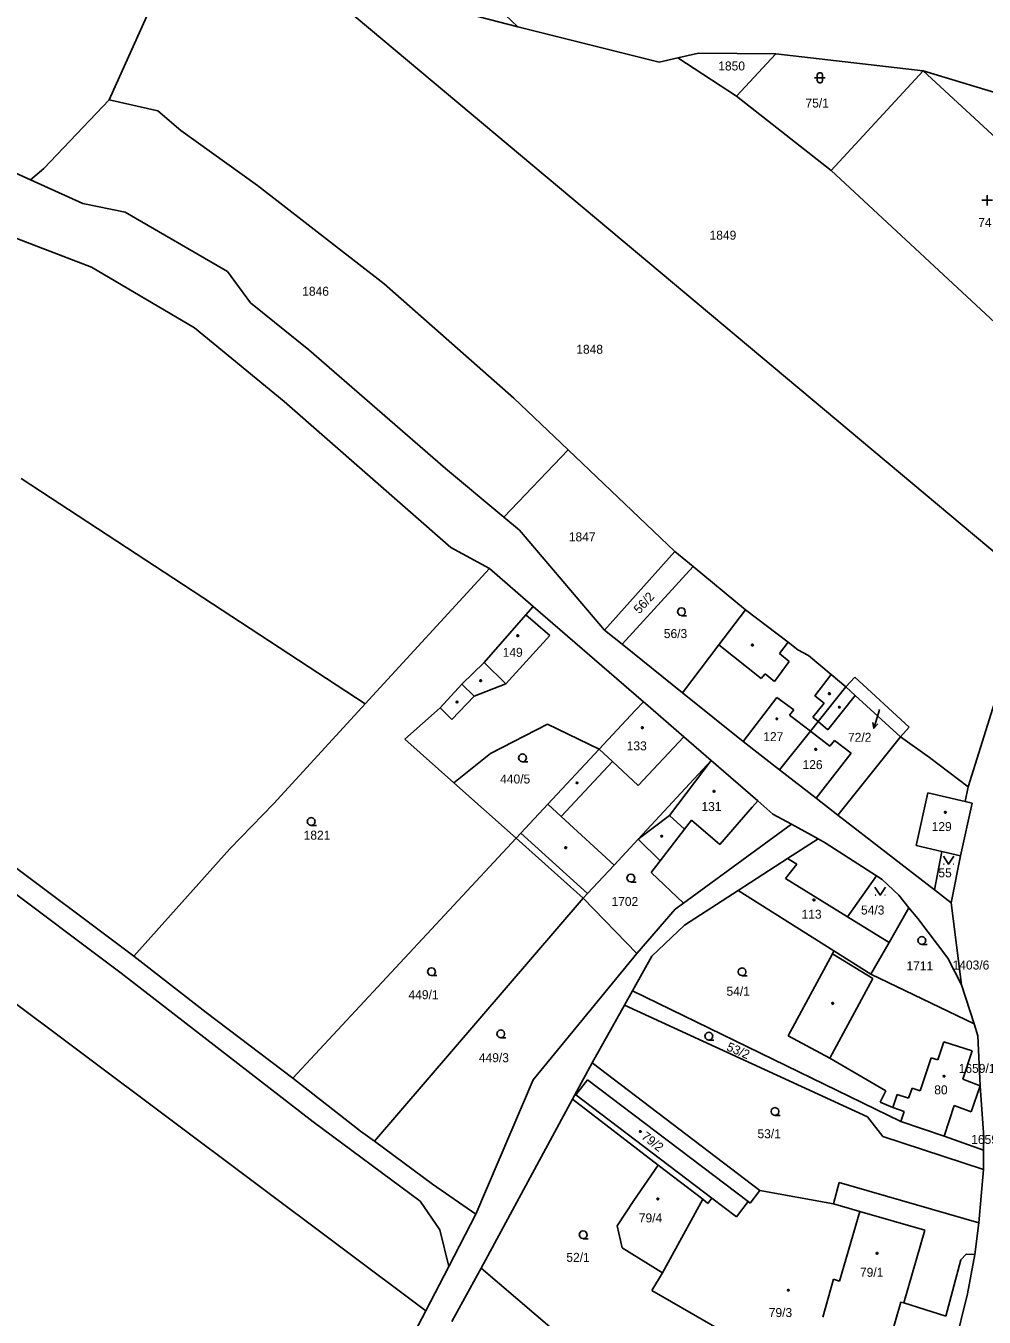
# Model space of a CAD drawing. Extents: x -802857 to -799647, y -1020285 to -1015884.
# Drawn here: x -801671.4 to -801490, y -1017493.5 to -1017248.9 of the extents above; entities that cross this region are included whole.
import ezdxf

# ---------------------------------------------------------------- set-up
doc = ezdxf.new("R2010")
doc.units = 0
for name, color, linetype in [('Default', 7, 'Continuous'), ('KN_HRANICE', 7, 'Continuous'), ('KN_KULTURY', 7, 'Continuous'), ('KN_PARCELY', 7, 'Continuous'), ('KN_SLUCKY', 7, 'Continuous'), ('Železniční svršek', 7, 'Continuous')]:
    doc.layers.add(name, color=color, linetype=linetype)

# ---------------------------------------------------------------- blocks, each defined once
blk = doc.blocks.new('304')
at = {"layer": 'Default'}
blk.add_lwpolyline([(0, 0), (-0.38, 0.1), (-0.65, 0.37), (-0.75, 0.74), (-0.65, 1.11), (-0.38, 1.38), (-0.01, 1.48), (0.36, 1.38), (0.63, 1.11), (0.73, 0.73), (0.63, 0.35), (0.36, 0.08), (-0.02, -0.02), (0.98, -0.02)], dxfattribs=at)
blk = doc.blocks.new('314')
at = {"layer": 'Default'}
for p, q in [((-0.95, 0), (-0.85, 0)), ((0.85, 0), (0.95, 0))]:
    blk.add_line(p, q, dxfattribs=at)
blk.add_lwpolyline([(-1, 1.5), (0, 0), (1, 1.5)], dxfattribs=at)
blk = doc.blocks.new('315')
at = {"layer": 'Default'}
for p, q in [((-1, 1), (1, 1)), ((0, 0), (0, 2))]:
    blk.add_line(p, q, dxfattribs=at)
blk = doc.blocks.new('316')
at = {"layer": 'Default'}
for points in [[(-1, 1), (0.27, 1), (1, 1)], [(-0.5, 1.5), (-0.4, 1.79), (-0.15, 1.97), (0.16, 1.97), (0.41, 1.79), (0.51, 1.5), (0.51, 0.5), (0.41, 0.21), (0.16, 0.03), (-0.15, 0.03), (-0.4, 0.21), (-0.5, 0.5), (-0.5, 1.5)]]:
    blk.add_lwpolyline(points, dxfattribs=at)
blk = doc.blocks.new('NAHRADNI_SYMBOL')
at = {"layer": 'Default'}
blk.add_lwpolyline([(0.09, 0.15), (0.18, 0), (0.09, -0.15), (-0.09, -0.15), (-0.18, 0), (-0.09, 0.15), (0.09, 0.15)], dxfattribs=at)
blk = doc.blocks.new('10292')
at = {"layer": 'Default'}
blk.add_line((0, 3), (0, 0), dxfattribs=at)
blk.add_lwpolyline([(-0.5, 2), (0, 3), (0.5, 2)], dxfattribs=at)
blk = doc.blocks.new('402')
at = {"layer": 'Default'}
blk.add_lwpolyline([(0.09, 0.15), (0.18, 0), (0.09, -0.15), (-0.09, -0.15), (-0.18, 0), (-0.09, 0.15), (0.09, 0.15)], dxfattribs=at)

msp = doc.modelspace()

# ---------------------------------------------------------------- linework, layer by layer
at = {"layer": 'KN_HRANICE'}
for p, q in [((-801655.6, -1017262.96), (-801641.91, -1017232.42)), ((-801619.51, -1017238.39), (-801481.95, -1017353.71)), ((-801578.28, -1017249.11), (-801619.51, -1017238.39)), ((-801578.28, -1017249.11), (-801586.61, -1017241.17)), ((-801551.48, -1017255.81), (-801578.28, -1017249.11)), ((-801551.48, -1017255.81), (-801547.98, -1017255)), ((-801547.98, -1017255), (-801544.09, -1017254.11)), ((-801536.89, -1017262.22), (-801547.98, -1017255)), ((-801544.09, -1017254.11), (-801529.45, -1017254.24)), ((-801529.45, -1017254.24), (-801536.89, -1017262.22)), ((-801501.56, -1017257.45), (-801529.45, -1017254.24)), ((-801518.94, -1017276.33), (-801501.56, -1017257.45)), ((-801477.73, -1017264.63), (-801501.56, -1017257.45)), ((-801466.82, -1017289.45), (-801501.56, -1017257.45)), ((-801655.6, -1017262.96), (-801668, -1017275.97)), ((-801646.39, -1017265.01), (-801655.6, -1017262.96)), ((-801518.94, -1017276.33), (-801536.89, -1017262.22)), ((-801642.06, -1017268.74), (-801646.39, -1017265.01)), ((-801627.56, -1017279.15), (-801642.06, -1017268.74)), ((-801678.51, -1017274.48), (-801670.52, -1017278.09)), ((-801668, -1017275.97), (-801670.52, -1017278.09)), ((-801473.28, -1017318.78), (-801518.94, -1017276.33)), ((-801670.52, -1017278.09), (-801660.59, -1017282.57)), ((-801603.57, -1017297.8), (-801627.56, -1017279.15)), ((-801658.95, -1017294.66), (-801692.48, -1017281.81)), ((-801660.59, -1017282.57), (-801652.6, -1017284.2)), ((-801652.6, -1017284.2), (-801633.2, -1017295.47)), ((-801639.5, -1017306.13), (-801658.95, -1017294.66)), ((-801633.2, -1017295.47), (-801628.86, -1017301.38)), ((-801579.02, -1017319.41), (-801603.57, -1017297.8)), ((-801628.86, -1017301.38), (-801617.81, -1017310.3)), ((-801622.51, -1017320.08), (-801639.5, -1017306.13)), ((-801617.81, -1017310.3), (-801591.97, -1017332.75)), ((-801802.71, -1017316.54), (-801653.38, -1017428.3)), ((-801568.75, -1017329.21), (-801579.02, -1017319.41)), ((-801590.96, -1017347.71), (-801622.51, -1017320.08)), ((-801568.75, -1017329.21), (-801580.94, -1017341.98)), ((-801548.54, -1017348.49), (-801568.75, -1017329.21)), ((-801591.97, -1017332.75), (-801580.94, -1017341.98)), ((-801771.82, -1017334.66), (-801650.93, -1017425.14)), ((-801672.29, -1017334.66), (-801607.17, -1017377.34)), ((-801580.94, -1017341.98), (-801577.98, -1017344.46)), ((-801577.98, -1017344.46), (-801561.84, -1017363.38)), ((-801583.62, -1017351.71), (-801590.96, -1017347.71)), ((-801561.84, -1017363.38), (-801548.54, -1017348.49)), ((-801548.54, -1017348.49), (-801545.1, -1017351.32)), ((-801607.17, -1017377.34), (-801583.62, -1017351.71)), ((-801575.39, -1017358.89), (-801583.62, -1017351.71)), ((-801558.54, -1017366.04), (-801545.1, -1017351.32)), ((-801535.15, -1017359.53), (-801545.1, -1017351.32)), ((-801584.63, -1017369.48), (-801576.74, -1017360.44)), ((-801576.74, -1017360.44), (-801575.39, -1017358.89)), ((-801575.39, -1017358.89), (-801554.48, -1017376.92)), ((-801540.19, -1017366.17), (-801535.15, -1017359.53)), ((-801527.11, -1017365.64), (-801535.15, -1017359.53)), ((-801558.54, -1017366.04), (-801561.84, -1017363.38)), ((-801527.11, -1017365.64), (-801525.25, -1017367.08)), ((-801547.08, -1017375.26), (-801558.54, -1017366.04)), ((-801547.08, -1017375.26), (-801540.19, -1017366.17)), ((-801525.25, -1017367.08), (-801523.25, -1017368.15)), ((-801518.94, -1017371.78), (-801523.25, -1017368.15)), ((-801588.89, -1017373.59), (-801584.63, -1017369.48)), ((-801493.03, -1017393.07), (-801486.04, -1017370.69)), ((-801516.17, -1017374.11), (-801518.94, -1017371.78)), ((-801514.48, -1017372.27), (-801516.17, -1017374.11)), ((-801514.48, -1017372.27), (-801504.16, -1017381.72)), ((-801592.99, -1017378.06), (-801588.89, -1017373.59)), ((-801535.63, -1017384.47), (-801547.08, -1017375.26)), ((-801521.42, -1017380.69), (-801516.17, -1017374.11)), ((-801516.17, -1017374.11), (-801514.41, -1017375.72)), ((-801624.47, -1017396.18), (-801607.17, -1017377.34)), ((-801599.68, -1017384.03), (-801592.99, -1017378.06)), ((-801556.07, -1017378.59), (-801554.48, -1017376.92)), ((-801554.48, -1017376.92), (-801554.09, -1017377.25)), ((-801546.85, -1017383.57), (-801554.09, -1017377.25)), ((-801514.41, -1017375.72), (-801505.85, -1017383.57)), ((-801562.88, -1017385.9), (-801556.07, -1017378.59)), ((-801572.67, -1017381.19), (-801583.43, -1017386.73)), ((-801572.67, -1017381.19), (-801562.88, -1017385.9)), ((-801528.72, -1017389.84), (-801522.87, -1017382.51)), ((-801522.87, -1017382.51), (-801521.42, -1017380.69)), ((-801504.16, -1017381.72), (-801505.85, -1017383.57)), ((-801590.38, -1017392.28), (-801599.68, -1017384.03)), ((-801541.65, -1017388.03), (-801546.85, -1017383.57)), ((-801535.63, -1017384.47), (-801528.72, -1017389.84)), ((-801517.7, -1017398.38), (-801505.85, -1017383.57)), ((-801505.85, -1017383.57), (-801500.35, -1017387.46)), ((-801583.43, -1017386.73), (-801590.38, -1017392.28)), ((-801572.59, -1017396.33), (-801562.88, -1017385.9)), ((-801500.35, -1017387.46), (-801493.03, -1017393.07)), ((-801555.48, -1017402.95), (-801541.65, -1017388.03)), ((-801541.65, -1017388.03), (-801532.86, -1017395.69)), ((-801528.72, -1017389.84), (-801521.8, -1017395.21)), ((-801578.57, -1017402.75), (-801590.38, -1017392.28)), ((-801521.8, -1017395.21), (-801517.7, -1017398.38)), ((-801493.03, -1017393.07), (-801493.56, -1017395.81)), ((-801632.76, -1017404.81), (-801624.47, -1017396.18)), ((-801577.72, -1017401.84), (-801572.59, -1017396.33)), ((-801532.86, -1017395.69), (-801529.98, -1017398.2)), ((-801494.46, -1017406.11), (-801492.26, -1017396.11)), ((-801492.26, -1017396.11), (-801493.56, -1017395.81)), ((-801526.45, -1017400.14), (-801546.89, -1017415.08)), ((-801529.98, -1017398.2), (-801526.45, -1017400.14)), ((-801526.45, -1017400.14), (-801521.42, -1017402.91)), ((-801499.39, -1017412.56), (-801517.7, -1017398.38)), ((-801717.22, -1017401.3), (-801595.69, -1017492.25)), ((-801578.57, -1017402.75), (-801577.72, -1017401.84)), ((-801650.93, -1017425.14), (-801632.76, -1017404.81)), ((-801578.57, -1017402.75), (-801620.86, -1017448.21)), ((-801578.57, -1017402.75), (-801565.92, -1017414.14)), ((-801560.03, -1017407.86), (-801555.48, -1017402.95)), ((-801551.33, -1017407.06), (-801555.48, -1017402.95)), ((-801521.42, -1017402.91), (-801527.19, -1017406.63)), ((-801521.42, -1017402.91), (-801520.08, -1017403.65)), ((-801520.08, -1017403.65), (-801510.35, -1017409.92)), ((-801551.33, -1017407.06), (-801553.03, -1017409.26)), ((-801527.19, -1017406.63), (-801536.56, -1017412.68)), ((-801497.98, -1017405.3), (-801499.39, -1017412.56)), ((-801494.46, -1017406.11), (-801497.98, -1017405.3)), ((-801496.25, -1017414.99), (-801494.46, -1017406.11)), ((-801565.05, -1017413.25), (-801560.03, -1017407.86)), ((-801553.03, -1017409.26), (-801546.89, -1017415.08)), ((-801515.86, -1017417.69), (-801510.35, -1017409.92)), ((-801510.35, -1017409.92), (-801509.28, -1017410.61)), ((-801506.17, -1017413.59), (-801509.28, -1017410.61)), ((-801605.43, -1017460.13), (-801565.92, -1017414.14)), ((-801565.92, -1017414.14), (-801565.05, -1017413.25)), ((-801565.92, -1017414.14), (-801555.75, -1017424.58)), ((-801536.56, -1017412.68), (-801546.71, -1017419.24)), ((-801518.43, -1017424.13), (-801536.56, -1017412.68)), ((-801504.24, -1017415.93), (-801506.17, -1017413.59)), ((-801496.25, -1017414.99), (-801499.39, -1017412.56)), ((-801548.47, -1017416.23), (-801555.75, -1017424.58)), ((-801546.89, -1017415.08), (-801548.47, -1017416.23)), ((-801504.24, -1017415.93), (-801507.97, -1017422.53)), ((-801502.53, -1017418), (-801504.24, -1017415.93)), ((-801496.25, -1017414.99), (-801494.3, -1017430.54)), ((-801546.71, -1017419.24), (-801552.91, -1017425.1)), ((-801515.86, -1017417.69), (-801507.97, -1017422.53)), ((-801496.87, -1017425.51), (-801502.53, -1017418)), ((-801555.75, -1017424.58), (-801575.39, -1017448.51)), ((-801518.43, -1017424.13), (-801518.7, -1017424.64)), ((-801511.47, -1017428.53), (-801518.43, -1017424.13)), ((-801507.97, -1017422.53), (-801511.47, -1017428.53)), ((-801637.26, -1017435.75), (-801650.93, -1017425.14)), ((-801552.91, -1017425.1), (-801556.57, -1017431.67)), ((-801518.7, -1017424.64), (-801527.1, -1017440.22)), ((-801494.3, -1017430.54), (-801496.87, -1017425.51)), ((-801617.04, -1017456.51), (-801653.38, -1017428.3)), ((-801511.47, -1017428.53), (-801491.9, -1017437.9)), ((-801556.57, -1017431.67), (-801558.1, -1017434.4)), ((-801505.75, -1017456.45), (-801556.57, -1017431.67)), ((-801494.3, -1017430.54), (-801491.9, -1017437.9)), ((-801558.1, -1017434.4), (-801564.2, -1017445.34)), ((-801512.08, -1017455.55), (-801558.1, -1017434.4)), ((-801620.86, -1017448.21), (-801637.26, -1017435.75)), ((-801491.9, -1017437.9), (-801491.16, -1017440.19)), ((-801527.1, -1017440.22), (-801519.19, -1017444.45)), ((-801490.73, -1017449.68), (-801491.16, -1017440.19)), ((-801564.2, -1017445.34), (-801567.91, -1017452.2)), ((-801564.2, -1017445.34), (-801532.43, -1017469.46)), ((-801519.19, -1017444.45), (-801508.59, -1017450.64)), ((-801608.02, -1017458.26), (-801620.86, -1017448.21)), ((-801575.39, -1017448.51), (-801586.22, -1017473.94)), ((-801508.59, -1017450.64), (-801509.67, -1017452.75)), ((-801490.73, -1017449.68), (-801490.02, -1017459.44)), ((-801567.91, -1017452.2), (-801585.19, -1017484.18)), ((-801551.71, -1017464.66), (-801567.91, -1017452.2)), ((-801509.67, -1017452.75), (-801507.29, -1017453.78)), ((-801505.11, -1017454.5), (-801507.29, -1017453.78)), ((-801512.08, -1017455.55), (-801509.17, -1017459.29)), ((-801505.75, -1017456.45), (-801505.11, -1017454.5)), ((-801596.78, -1017471.51), (-801617.04, -1017456.51)), ((-801605.43, -1017460.13), (-801608.02, -1017458.26)), ((-801505.75, -1017456.45), (-801497.54, -1017459.17)), ((-801594.4, -1017468.3), (-801605.43, -1017460.13)), ((-801509.17, -1017459.29), (-801490.11, -1017465.48)), ((-801497.54, -1017459.17), (-801490.11, -1017461.87)), ((-801490.02, -1017459.44), (-801490.11, -1017461.87)), ((-801490.11, -1017461.87), (-801490.11, -1017465.48)), ((-801556.33, -1017471.36), (-801551.71, -1017464.66)), ((-801543.26, -1017471.16), (-801551.71, -1017464.66)), ((-801490.11, -1017465.48), (-801491, -1017475.58)), ((-801586.22, -1017473.94), (-801594.4, -1017468.3)), ((-801517.41, -1017467.99), (-801518.51, -1017471.99)), ((-801491, -1017475.58), (-801517.41, -1017467.99)), ((-801541.51, -1017470.93), (-801542.27, -1017471.92)), ((-801536.86, -1017474.46), (-801541.51, -1017470.93)), ((-801534.26, -1017471.87), (-801532.43, -1017469.46)), ((-801518.51, -1017471.99), (-801532.43, -1017469.46)), ((-801596.78, -1017471.51), (-801593.04, -1017476.93)), ((-801559.45, -1017476.19), (-801556.33, -1017471.36)), ((-801550.85, -1017485.09), (-801543.26, -1017471.16)), ((-801542.27, -1017471.92), (-801543.26, -1017471.16)), ((-801534.66, -1017471.57), (-801536.86, -1017474.46)), ((-801534.66, -1017471.57), (-801534.26, -1017471.87)), ((-801513.5, -1017473.44), (-801518.51, -1017471.99)), ((-801513.5, -1017473.44), (-801517.36, -1017486.64)), ((-801591.35, -1017483.86), (-801586.22, -1017473.94)), ((-801491, -1017475.58), (-801491.75, -1017481.58)), ((-801593.04, -1017476.93), (-801591.35, -1017483.86)), ((-801558.54, -1017480.37), (-801559.45, -1017476.19)), ((-801558.54, -1017480.37), (-801550.85, -1017485.09)), ((-801494.38, -1017482.64), (-801497.27, -1017493.26)), ((-801493.41, -1017481.55), (-801494.38, -1017482.64)), ((-801491.75, -1017481.58), (-801493.41, -1017481.55)), ((-801491.75, -1017481.58), (-801493.16, -1017489.06)), ((-801595.69, -1017492.25), (-801591.35, -1017483.86)), ((-801590.76, -1017494.27), (-801585.19, -1017484.18)), ((-801585.19, -1017484.18), (-801552, -1017512.59)), ((-801552.91, -1017488.45), (-801550.85, -1017485.09)), ((-801518.48, -1017486.31), (-801520.55, -1017493.48)), ((-801517.36, -1017486.64), (-801518.48, -1017486.31)), ((-801538.03, -1017497.01), (-801552.91, -1017488.45)), ((-801505.75, -1017490.62), (-801507.63, -1017497.2)), ((-801505.18, -1017490.78), (-801505.75, -1017490.62)), ((-801493.16, -1017489.06), (-801499.29, -1017513.8)), ((-801603.69, -1017507.7), (-801595.69, -1017492.25)), ((-801497.27, -1017493.26), (-801505.18, -1017490.78))]:
    msp.add_line(p, q, dxfattribs=at)
at = {"layer": 'KN_PARCELY'}
msp.add_line((-801509.8, -1017378.42), (-801510, -1017379.07), dxfattribs=at)
at = {"layer": 'KN_SLUCKY'}
for p, q in [((-801572.2, -1017364.41), (-801576.74, -1017360.44)), ((-801572.2, -1017364.41), (-801580.56, -1017373.52)), ((-801528.73, -1017367.8), (-801527.11, -1017365.64)), ((-801532.21, -1017372.54), (-801540.19, -1017366.17)), ((-801526.9, -1017369.29), (-801528.73, -1017367.8)), ((-801584.63, -1017369.48), (-801580.56, -1017373.52)), ((-801526.9, -1017369.29), (-801529.68, -1017373.09)), ((-801531.47, -1017371.63), (-801532.21, -1017372.54)), ((-801529.68, -1017373.09), (-801531.47, -1017371.63)), ((-801518.94, -1017371.78), (-801522.04, -1017375.81)), ((-801588.89, -1017373.59), (-801586.56, -1017375.88)), ((-801586.56, -1017375.88), (-801580.56, -1017373.52)), ((-801592.99, -1017378.06), (-801590.78, -1017380.31)), ((-801586.56, -1017375.88), (-801590.78, -1017380.31)), ((-801529.25, -1017376.14), (-801535.63, -1017384.47)), ((-801525.99, -1017378.48), (-801529.25, -1017376.14)), ((-801522.39, -1017379.87), (-801520.3, -1017377.18)), ((-801520.3, -1017377.18), (-801522.04, -1017375.81)), ((-801514.41, -1017375.72), (-801519.61, -1017382.22)), ((-801526.82, -1017379.48), (-801525.99, -1017378.48)), ((-801522.87, -1017382.51), (-801526.82, -1017379.48)), ((-801521.42, -1017380.69), (-801522.39, -1017379.87)), ((-801519.17, -1017385.35), (-801522.87, -1017382.51)), ((-801519.61, -1017382.22), (-801521.42, -1017380.69)), ((-801546.85, -1017383.57), (-801555.5, -1017392.82)), ((-801518.31, -1017384.26), (-801519.17, -1017385.35)), ((-801515.18, -1017386.69), (-801518.31, -1017384.26)), ((-801560.37, -1017388.25), (-801562.88, -1017385.9)), ((-801521.8, -1017395.21), (-801515.18, -1017386.69)), ((-801570.07, -1017398.64), (-801560.37, -1017388.25)), ((-801555.5, -1017392.82), (-801560.37, -1017388.25)), ((-801541.65, -1017388.03), (-801549.55, -1017398.5)), ((-801500.66, -1017394.18), (-801502.86, -1017404.18)), ((-801493.56, -1017395.81), (-801500.66, -1017394.18)), ((-801570.07, -1017398.64), (-801572.59, -1017396.33)), ((-801540.01, -1017403.98), (-801533.91, -1017396.9)), ((-801532.86, -1017395.69), (-801533.91, -1017396.9)), ((-801560.03, -1017407.86), (-801570.07, -1017398.64)), ((-801549.55, -1017398.5), (-801555.48, -1017402.95)), ((-801549.55, -1017398.5), (-801546.7, -1017401.04)), ((-801545.41, -1017399.37), (-801546.7, -1017401.04)), ((-801540.01, -1017403.98), (-801545.41, -1017399.37)), ((-801565.05, -1017413.25), (-801577.72, -1017401.84)), ((-801546.7, -1017401.04), (-801551.33, -1017407.06)), ((-801497.98, -1017405.3), (-801502.86, -1017404.18)), ((-801525.46, -1017407.68), (-801527.19, -1017406.63)), ((-801527.6, -1017410.39), (-801525.46, -1017407.68)), ((-801515.86, -1017417.69), (-801527.6, -1017410.39)), ((-801511.05, -1017429.33), (-801518.7, -1017424.64)), ((-801511.05, -1017429.33), (-801519.19, -1017444.45)), ((-801498.77, -1017444.75), (-801497.63, -1017441.33)), ((-801497.63, -1017441.33), (-801492.28, -1017443.05)), ((-801492.28, -1017443.05), (-801494.03, -1017448.42)), ((-801502.08, -1017450.61), (-801500, -1017444.34)), ((-801500, -1017444.34), (-801498.77, -1017444.75)), ((-801567.28, -1017451.37), (-801565.08, -1017448.53)), ((-801565.08, -1017448.53), (-801534.66, -1017471.57)), ((-801494.03, -1017448.42), (-801490.73, -1017449.68)), ((-801541.51, -1017470.93), (-801567.28, -1017451.37)), ((-801507.29, -1017453.78), (-801506.47, -1017451.31)), ((-801506.47, -1017451.31), (-801504.29, -1017452.03)), ((-801504.29, -1017452.03), (-801503.64, -1017450.09)), ((-801503.64, -1017450.09), (-801502.08, -1017450.61)), ((-801490.73, -1017449.68), (-801492.46, -1017454.58)), ((-801495.65, -1017453.37), (-801497.54, -1017459.17)), ((-801495.65, -1017453.37), (-801492.46, -1017454.58)), ((-801501.2, -1017476.98), (-801513.5, -1017473.44)), ((-801505.18, -1017490.78), (-801501.2, -1017476.98))]:
    msp.add_line(p, q, dxfattribs=at)
at = {"layer": 'Železniční svršek'}
msp.add_arc((-801431.93, -1016905.94), 345.8, 259.1164, 305.4132, dxfattribs=at)

# ---------------------------------------------------------------- block references
at = {"layer": 'KN_KULTURY'}
for name, p in [('316', (-801521.08, -1017259.77)), ('315', (-801489.43, -1017282.97)), ('304', (-801547.29, -1017360.61)), ('402', (-801578.28, -1017364.41)), ('402', (-801533.86, -1017366.18)), ('402', (-801585.3, -1017372.96)), ('402', (-801519.28, -1017375.38)), ('402', (-801589.78, -1017376.97)), ('402', (-801517.38, -1017377.96)), ('402', (-801529.23, -1017380.16)), ('402', (-801554.7, -1017381.85)), ('304', (-801577.38, -1017388.3)), ('402', (-801521.86, -1017385.94)), ('402', (-801567.06, -1017392.28)), ('402', (-801541.13, -1017393.89)), ('402', (-801497.34, -1017397.85)), ('304', (-801617.39, -1017400.35)), ('402', (-801551.02, -1017402.39)), ('402', (-801569.2, -1017404.58)), ('314', (-801496.71, -1017407.69)), ('304', (-801556.85, -1017411.05)), ('314', (-801509.66, -1017413.55)), ('402', (-801522.21, -1017414.48)), ('304', (-801501.78, -1017422.88)), ('304', (-801594.6, -1017428.78)), ('304', (-801535.81, -1017428.8)), ('402', (-801518.66, -1017434.02)), ('304', (-801581.49, -1017440.56)), ('304', (-801542.11, -1017441)), ('402', (-801497.57, -1017447.84)), ('304', (-801529.58, -1017455.26)), ('402', (-801555.05, -1017458.31)), ('NAHRADNI_SYMBOL', (-801551.76, -1017471.1)), ('304', (-801565.9, -1017478.59)), ('402', (-801510.27, -1017481.38)), ('NAHRADNI_SYMBOL', (-801527.06, -1017488.37))]:
    msp.add_blockref(name, p, dxfattribs=at)
at = {"layer": 'KN_PARCELY', "rotation": 162.949197}
msp.add_blockref('10292', (-801510, -1017379.07), dxfattribs=at)

# ---------------------------------------------------------------- texts
at = {"layer": 'KN_PARCELY'}
for s, height, p in [('1850', 1.7, (-801540.32, -1017257.38)), ('75/1', 1.7, (-801523.81, -1017264.4)), ('74', 1.7, (-801491.11, -1017287.01)), ('1849', 1.7, (-801541.97, -1017289.42)), ('1846', 1.7, (-801619.08, -1017300.04)), ('1848', 1.7, (-801567.2, -1017311.03)), ('1847', 1.7, (-801568.61, -1017346.56)), ('56/3', 1.7, (-801550.63, -1017364.87)), ('149', 1.7, (-801581.13, -1017368.42)), ('72/2', 0.1, (-801510, -1017378.42)), ('127', 1.7, (-801531.8, -1017384.39)), ('72/2', 1.7, (-801515.76, -1017384.52)), ('133', 1.7, (-801557.65, -1017386.13)), ('126', 1.7, (-801524.37, -1017389.69)), ('440/5', 1.7, (-801581.61, -1017392.41)), ('131', 1.7, (-801543.51, -1017397.63)), ('129', 1.7, (-801499.92, -1017401.42)), ('1821', 1.7, (-801618.81, -1017403.05)), ('55', 1.7, (-801498.65, -1017410.17)), ('1702', 1.7, (-801560.53, -1017415.61)), ('113', 1.7, (-801524.56, -1017418.02)), ('54/3', 1.7, (-801513.3, -1017417.22)), ('1711', 1.7, (-801504.7, -1017427.81)), ('1403/6', 1.7, (-801495.96, -1017427.64)), ('449/1', 1.7, (-801598.96, -1017433.26)), ('54/1', 1.7, (-801538.76, -1017432.61)), ('449/3', 1.7, (-801585.64, -1017445.19)), ('1659/17', 1.7, (-801494.8, -1017447.21)), ('80', 1.7, (-801499.43, -1017451.28)), ('53/1', 1.7, (-801532.9, -1017459.59)), ('1659/4', 1.7, (-801492.44, -1017460.67)), ('79/4', 1.7, (-801555.36, -1017475.53)), ('52/1', 1.7, (-801569.08, -1017483)), ('79/1', 1.7, (-801513.49, -1017485.83)), ('79/3', 1.7, (-801530.76, -1017493.45))]:
    msp.add_text(s, height=height, dxfattribs=at).set_placement(p)
for s, rotation, p in [('56/2', 47.785, (-801555.26, -1017360.4)), ('53/2', 336.613, (-801538.89, -1017442.9)), ('79/2', 321.716, (-801555, -1017459.52))]:
    msp.add_text(s, height=1.7, rotation=rotation, dxfattribs=at).set_placement(p)

doc.saveas('drawing.dxf')
